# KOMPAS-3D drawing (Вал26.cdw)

Referenced files in C:\Users\Polly\AppData\Local\Temp\: kfqlybda.cd
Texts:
  Вал
  kolly
  Ra0.8
  D-6x26x32js6x6f8
  2. * Размер обеспечивается инструментом
  3. ГОСТ 30893.1-т
  Ra3.2
  Ra6.3
  Ra0.4
  R 0,4max
  Ra12.5
  Ra12.5 ( )
  Егорова П.В.
  Макарова Т.А.
  Сталь40Х ГОСТ 4543-71
  СПбГПУ
  гр. В33321/1
Dimensions and other numbers on the sheet: 35; 42; 38; 30; 1,6; 3 фаски; 304; 238; 34; 45; 0.01; 1. 260...285 HB; 165; 0,010; 0,006; 5; 10; 0,004; 0,012; 0.008; 8; 0,002; 0,003; 1:1; 1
